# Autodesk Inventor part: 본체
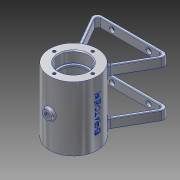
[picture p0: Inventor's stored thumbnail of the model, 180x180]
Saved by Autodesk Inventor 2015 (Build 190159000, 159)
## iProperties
Created: 2016-03
Part Number: 본체
Material: 알루미늄 6061
Document SubType Name: Modeling
Designer: Administrator
Density: 2.7 g/cm^3
Appearance: 알루미늄 - 평지
Mass: 212.731 g
Surface Area: 333.697 cm^2
Volume: 78.7893 cm^3
Author: Administrator
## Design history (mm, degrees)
sketch "스케치1"
  geometry: C1 r 26 at (0, 0); 1 further point
  constraints: 1 centre point, 1 coincident
  dimensions: "d0" = 52 diameter of C1
extrude "돌출1" new body sketch "스케치1" stored distance "d1" = 70; taper "d2" = 0 deg
node "작업 평면1"
sketch "스케치2"
  geometry: C1 r 6 at (0, 0); 1 further point
  constraints: 1 centre point, 1 coincident
  dimensions: "d4" = 12 diameter of C1
extrude "돌출2" join sketch "스케치2" distance "d5" = 29; taper "d6" = 0 deg
node "작업 평면2"
sketch "스케치3"
  geometry: L1 (42.594, 65)-(-42.594, 65); L2 (-16.613, 20)-(-42.594, 65); L3 (-16.613, 20)-(20.718, 20); L4 (16.613, 20)-(42.594, 65); L5 (16.613, 20)-(68.575, 20); L6 (14.183, 21.791)-(37.398, 62); L7 (37.398, 62)-(-37.398, 62); L8 (-37.398, 62)-(-14.183, 21.791); A1 r 26 centre (0, 0) between (16.613, 20) and (-16.613, 20) reference; 1 further point
  constraints: 16 end point, 4 point on circle, 3 horizontal, 1 equal length, 1 point on line
  dimensions: "d8" = 65 distance from line of point (0, 0) L1; "d10" = 120 deg angle of L3 L2; "d11" = 60 deg angle of L5 L4; "d12" = 3 distance between parallel lines of L2 L8
extrude "돌출3" join sketch "스케치3" distance "d13" = 10; taper "d14" = 0 deg
sketch "스케치4"
  geometry: C1 r 3 at (22.594, 5); C2 r 3 at (62.594, 5); 2 further points
  constraints: 2 centre point
  dimensions: "d15" = 6 diameter of C1; "d16" = 6 diameter of C2; "d17" = 5 vertical distance of point (0, 10) C1.centre; "d18" = 20 horizontal distance of point (42.594, -20) C1.centre; "d19" = 20 horizontal distance of C2.centre point (42.594, -20)
extrude "돌출4" cut sketch "스케치4" stored distance "d20" = 10; taper "d21" = 0 deg
fillet "모깎기1" dims "d22" = 5, "d23" = 3
sketch "스케치5"
  geometry: C1 r 26 at (0, 0) reference; C2 r 16 at (0, 0)
  constraints: 1 centre point, 1 coincident
  dimensions: "d24" = 32 diameter of C2
extrude "돌출5" cut sketch "스케치5" distance "d25" = 12; taper "d26" = 0 deg
sketch "스케치6"
  geometry: C1 r 16 at (0, 0) reference; C2 r 14 at (0, 0)
  constraints: 1 centre point, 1 coincident
  dimensions: "d27" = 28 diameter of C2
extrude "돌출6" cut sketch "스케치6" distance "d28" = 2; taper "d29" = 0 deg
sketch "스케치7"
  geometry: C1 r 14 at (0, 0) reference; C2 r 21 at (0, 0)
  constraints: 1 centre point, 1 coincident
  dimensions: "d30" = 42 diameter of C2
extrude "돌출7" cut sketch "스케치7" distance "d31" = 42; taper "d32" = 0 deg
sketch "스케치8"
  geometry: C1 r 26 at (0, 0) reference; C2 r 16 at (0, 0)
  constraints: 1 centre point, 1 coincident
  dimensions: "d33" = 32 diameter of C2
extrude "돌출8" cut sketch "스케치8" distance "d34" = 12; taper "d35" = 0 deg
sketch "스케치9"
  geometry: C1 r 16 at (0, 0) reference; C2 r 14 at (0, 0)
  constraints: 1 centre point, 1 coincident
  dimensions: "d36" = 28 diameter of C2
extrude "돌출9" cut sketch "스케치9" distance "d37" = 2; taper "d38" = 0 deg
node "작업 평면3"
sketch "스케치10"
  geometry: C1 r 5 at (0, 0); 1 further point
  constraints: 1 centre point, 1 coincident
  dimensions: "d40" = 10 diameter of C1
extrude "돌출10" join sketch "스케치10" stored distance "d41" = 2; taper "d42" = 0 deg
sketch "스케치11"
  geometry: C1 r 5 at (0, 0) reference; 1 further point
  constraints: 1 coincident
hole "구멍1" sketch "스케치11" at (0, 0) diameter "d43" = 5.188; stored, may be unused: countersink angle "d47" = 90 deg, drill point angle "d49" = 118 deg; dims "d44" = 12, "d45" = 4, "d46" = 2, "d48" = 16
sketch "스케치12"
  geometry: C1 r 6 at (0, 0) reference; 1 further point
  constraints: 1 coincident
hole "구멍2" sketch "스케치12" at (0, 0) diameter "d50" = 5.188; stored, may be unused: countersink angle "d54" = 90 deg, drill point angle "d56" = 118 deg; dims "d51" = 12, "d52" = 4, "d53" = 2, "d55" = 16
fillet "모깎기2" dims "d57" = 2
sketch "스케치13"
  geometry: C1 r 16 at (0, 0) reference; 4 further points
  constraints: 5 other
  dimensions: "d58" = 21 distance of C1.centre point (0, -21); "d61" = 360 deg dimension on C1.centre point (0, -21) (derived)
hole "구멍3" sketch "스케치13" at (0, -21), (21, 0), (0, 21), (-21, 0) diameter "d63" = 3.242; stored, may be unused: countersink angle "d67" = 90 deg, drill point angle "d69" = 118 deg; dims "d64" = 8, "d65" = 4, "d66" = 2, "d68" = 10
fillet "모깎기3" dims "d70" = 0.5
fillet "모깎기4" dims "d71" = 3
fillet "모깎기5" dims "d72" = 0.5
fillet "모깎기6" dims "d73" = 3
node "작업 평면4"
sketch "스케치15"
  geometry: L1 (-26, -35)-(26, -35) reference; 2 further points
  constraints: 1 other
  dimensions: "d77" = 35 distance from line of L1 point (0, 0); "d78" = 26 horizontal distance of L1.start point (0, 0)
feature "엠보싱1" sketch "스케치15" dims "d79" = 0.5, "d80" = 0
chamfer "모따기1" distance "d81" = 1; stored, may be unused: second distance "d82" = 2, angle "d83" = 45 deg
fillet "모깎기7" dims "d84" = 0.3
fillet "모깎기8" dims "d85" = 3
node "솔리드1"
mirror "대칭1"
mirror "대칭2"
mirror "대칭3"
other parameters: "d3" = 15 deg, "d39" = -29, "d74" = 26
